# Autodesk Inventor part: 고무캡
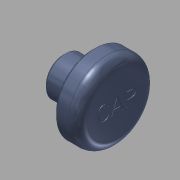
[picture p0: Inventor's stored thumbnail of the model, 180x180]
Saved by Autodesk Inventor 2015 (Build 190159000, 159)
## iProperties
Created: 2017-06
Part Number: 고무캡
Material: 고무
Document SubType Name: Modeling
Designer: mduedu
Density: 1 g/cm^3
Appearance: 고무 - 파란색 - 버전 1.1
Author: mduedu
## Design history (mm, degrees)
sketch "스케치1"
  geometry: L1 (0, 0)-(11, 0); L2 (11, 0)-(11, 8); L3 (11, 8)-(6.5, 8); L4 (0, 4)-(0, 0); L5 (0, 4)-(6, 4); L6 (6, 4)-(6, 7.5); L7 (6, 7.5)-(6.5, 7.5); L8 (6.5, 7.5)-(6.5, 8)
  constraints: 16 end point, 2 horizontal, 2 parallel, 2 perpendicular, 2 point on line, 1 vertical
  dimensions: "d0" = 16 diameter of L3 L1; "d2" = 8 diameter of L5 L1; "d6" = 5 distance between parallel lines of L2 L6; "d7" = 0.5 distance between parallel lines of L8 L6; "d8" = 15 diameter of L7 L1; "d9" = 6 distance between parallel lines of L6 L4
revolve "회전1" sketch "스케치1" stored, may be unused: angle "d10" = 90 deg
hole "구멍1" diameter "d22" = 5; stored, may be unused: countersink angle "d26" = 90 deg, drill point angle "d28" = 0 deg; dims "d23" = 6, "d24" = 4, "d25" = 2, "d27" = 6, "d30" = 10, "d31" = 10
chamfer "모따기1" distance "d13" = 0.5; stored, may be unused: second distance "d14" = 2, angle "d15" = 45 deg
fillet "모깎기3" dims "d29" = 1
fillet "모깎기1" dims "d16" = 0.1
fillet "모깎기2" dims "d17" = 2
sketch "스케치3"
  geometry: 2 further points
  constraints: 1 coincident, 1 other
feature "엠보싱1" sketch "스케치3" dims "d18" = 0.2, "d19" = 0
node "솔리드1"
